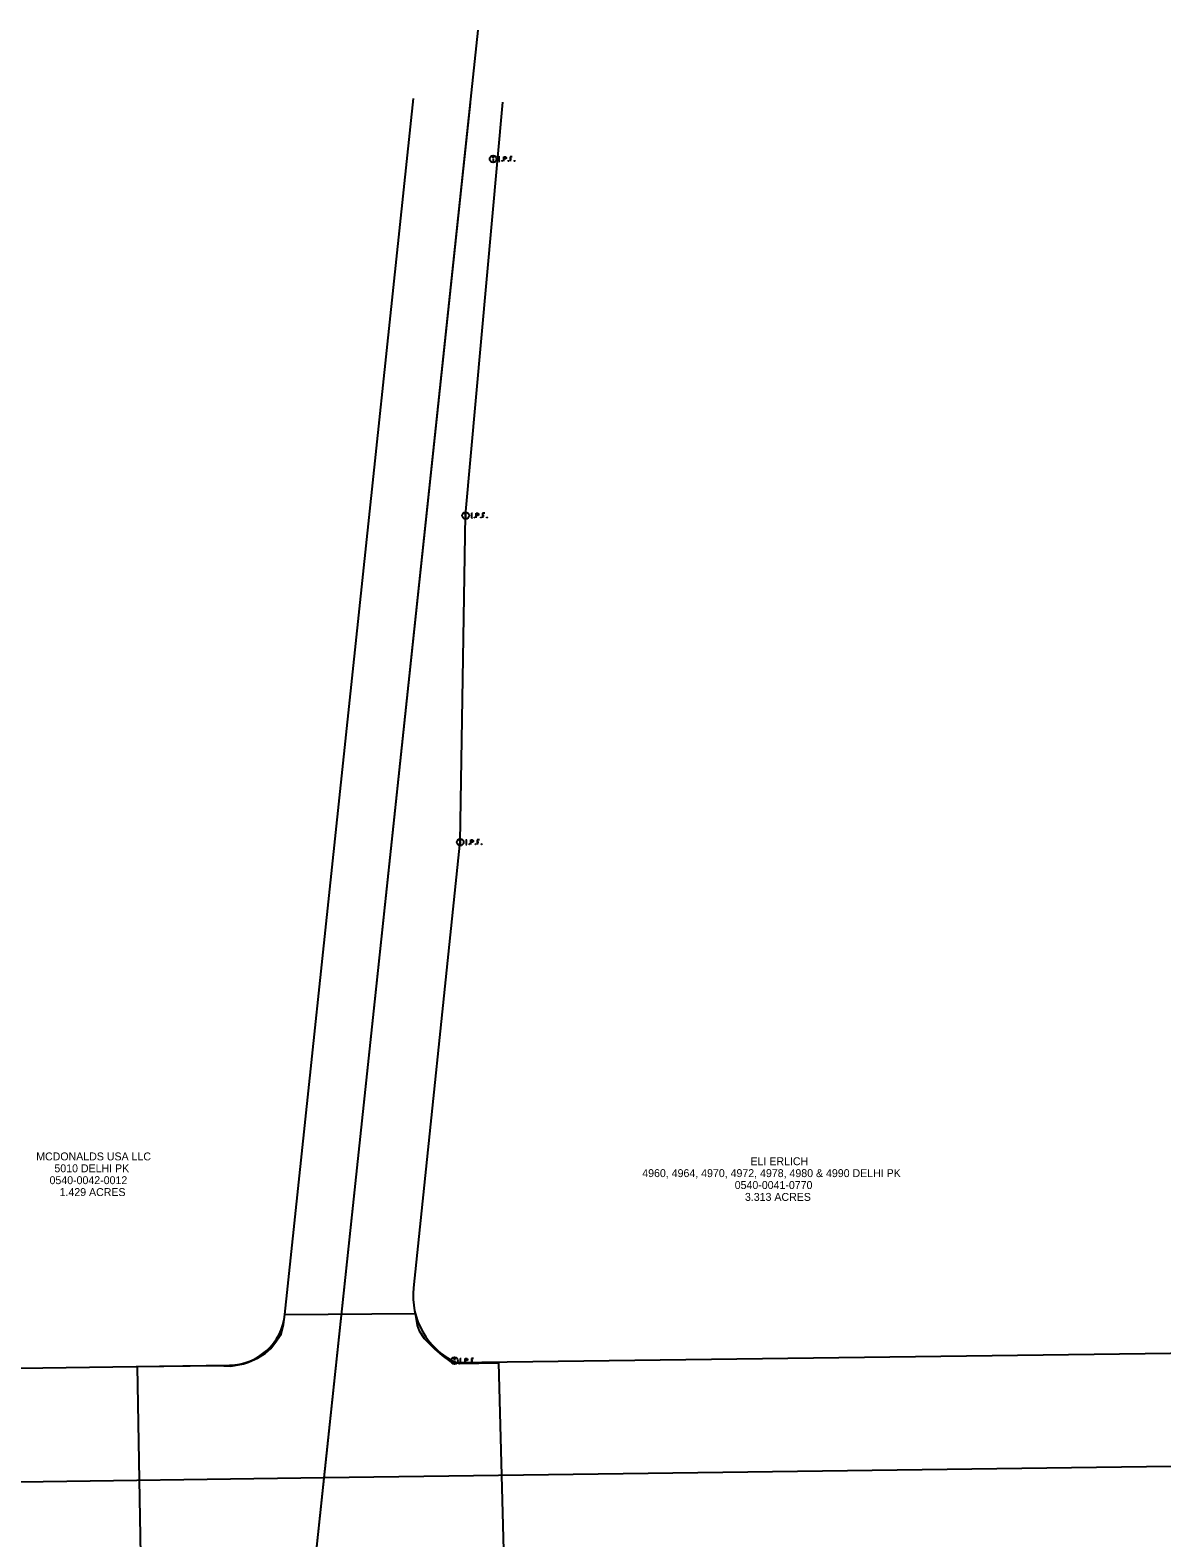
# Model space of a CAD drawing. Extents: x 1369159 to 1370720, y 404461 to 406422.
# Drawn here: x 1369920 to 1370320, y 405889 to 406422 of the extents above; entities that cross this region are included whole.
import ezdxf

# ---------------------------------------------------------------- set-up
doc = ezdxf.new("R2010")
doc.units = 0
for name, color, linetype in [('DR_P_Cells', 7, 'Continuous'), ('DR_X_Cells', 7, 'Continuous'), ('GK_Drainage_Nodes', 7, 'Continuous'), ('SC_Scratch1', 7, 'Continuous'), ('XS_X_Pavt', 7, 'Continuous'), ('XS_X_Subgrade', 7, 'Continuous')]:
    doc.layers.add(name, color=color, linetype=linetype)

msp = doc.modelspace()

# ---------------------------------------------------------------- linework, layer by layer
at = {"layer": 'DR_P_Cells'}
msp.add_line((1370077.92, 406421.94), (1369968.9, 405398.85), dxfattribs=at)
at = {"layer": 'DR_X_Cells'}
msp.add_lwpolyline([(1369959, 405869.67), (1369957.54, 405949.66), (1369985.54, 405950.07), (1369990.57, 405949.81), (1369995.08, 405950.56), (1369996.84, 405951.24), (1369999.97, 405952.63), (1370002.78, 405954.43), (1370004.68, 405955.98), (1370006.08, 405957.97), (1370008.33, 405961.08), (1370009.2, 405964.47), (1370009.68, 405968.04), (1370055.77, 405968.35), (1370056.38, 405964.22), (1370057.1, 405962.29), (1370058.87, 405959.59), (1370062.52, 405955.91), (1370065.31, 405953.6), (1370067.96, 405951.53), (1370070.19, 405951.11), (1370071.35, 405950.7), (1370085.17, 405950.93), (1370087.31, 405871.45)], dxfattribs=at)
at = {"layer": 'SC_Scratch1'}
for p, q in [((1370083.26, 406376.52), (1370083.26, 406375.64)), ((1370085.3, 406377.2), (1370085.65, 406377.2)), ((1370085.3, 406375.6), (1370085.65, 406375.6)), ((1370085.47, 406375.6), (1370085.47, 406377.2)), ((1370086.36, 406375.74), (1370086.4, 406375.79)), ((1370086.36, 406375.68), (1370086.36, 406375.74)), ((1370086.4, 406375.63), (1370086.36, 406375.68)), ((1370086.4, 406375.79), (1370086.43, 406375.82)), ((1370086.43, 406375.6), (1370086.4, 406375.63)), ((1370086.43, 406375.82), (1370086.49, 406375.82)), ((1370086.49, 406375.6), (1370086.43, 406375.6)), ((1370086.49, 406375.82), (1370086.52, 406375.79)), ((1370086.52, 406375.63), (1370086.49, 406375.6)), ((1370086.52, 406375.79), (1370086.55, 406375.74)), ((1370086.55, 406375.68), (1370086.52, 406375.63)), ((1370086.55, 406375.74), (1370086.55, 406375.68)), ((1370087.04, 406375.6), (1370087.04, 406377.2)), ((1370087.04, 406377.2), (1370087.57, 406377.2)), ((1370087.57, 406376.42), (1370087.04, 406376.42)), ((1370087.57, 406377.2), (1370087.62, 406377.19)), ((1370087.65, 406376.43), (1370087.57, 406376.42)), ((1370087.62, 406377.19), (1370087.7, 406377.16)), ((1370087.71, 406376.46), (1370087.65, 406376.43)), ((1370087.7, 406377.16), (1370087.73, 406377.14)), ((1370087.74, 406376.48), (1370087.71, 406376.46)), ((1370087.73, 406377.14), (1370087.76, 406377.11)), ((1370087.79, 406376.52), (1370087.74, 406376.48)), ((1370087.76, 406377.11), (1370087.81, 406377.05)), ((1370087.83, 406376.61), (1370087.79, 406376.52)), ((1370087.81, 406377.05), (1370087.84, 406376.99)), ((1370087.85, 406376.69), (1370087.83, 406376.61)), ((1370087.84, 406376.99), (1370087.86, 406376.89)), ((1370087.86, 406376.74), (1370087.85, 406376.69)), ((1370087.86, 406376.89), (1370087.86, 406376.74)), ((1370088.61, 406375.74), (1370088.65, 406375.79)), ((1370088.61, 406375.68), (1370088.61, 406375.74)), ((1370088.65, 406375.63), (1370088.61, 406375.68)), ((1370088.65, 406375.79), (1370088.68, 406375.82)), ((1370088.68, 406375.6), (1370088.65, 406375.63)), ((1370088.68, 406375.82), (1370088.73, 406375.82)), ((1370088.73, 406375.6), (1370088.68, 406375.6)), ((1370088.73, 406375.82), (1370088.77, 406375.79)), ((1370088.77, 406375.63), (1370088.73, 406375.6)), ((1370088.77, 406375.79), (1370088.8, 406375.74)), ((1370088.8, 406375.68), (1370088.77, 406375.63)), ((1370088.8, 406375.74), (1370088.8, 406375.68)), ((1370090.05, 406377.2), (1370089.29, 406377.2)), ((1370089.29, 406377.2), (1370089.29, 406375.6)), ((1370089.29, 406376.42), (1370089.83, 406376.42)), ((1370090.76, 406375.74), (1370090.8, 406375.79)), ((1370090.76, 406375.68), (1370090.76, 406375.74)), ((1370090.8, 406375.63), (1370090.76, 406375.68)), ((1370090.8, 406375.79), (1370090.83, 406375.82)), ((1370090.83, 406375.6), (1370090.8, 406375.63)), ((1370090.83, 406375.82), (1370090.88, 406375.82)), ((1370090.88, 406375.6), (1370090.83, 406375.6)), ((1370090.88, 406375.82), (1370090.92, 406375.79)), ((1370090.92, 406375.63), (1370090.88, 406375.6)), ((1370090.92, 406375.79), (1370090.95, 406375.74)), ((1370090.95, 406375.68), (1370090.92, 406375.63)), ((1370090.95, 406375.74), (1370090.95, 406375.68)), ((1370073.55, 406250.51), (1370073.55, 406249.63)), ((1370075.58, 406251.2), (1370075.94, 406251.2)), ((1370075.58, 406249.6), (1370075.94, 406249.6)), ((1370075.76, 406249.6), (1370075.76, 406251.2)), ((1370076.65, 406249.73), (1370076.69, 406249.79)), ((1370076.65, 406249.67), (1370076.65, 406249.73)), ((1370076.69, 406249.62), (1370076.65, 406249.67)), ((1370076.69, 406249.79), (1370076.72, 406249.81)), ((1370076.72, 406249.6), (1370076.69, 406249.62)), ((1370076.72, 406249.81), (1370076.77, 406249.81)), ((1370076.77, 406249.6), (1370076.72, 406249.6)), ((1370076.77, 406249.81), (1370076.81, 406249.79)), ((1370076.81, 406249.62), (1370076.77, 406249.6)), ((1370076.81, 406249.79), (1370076.84, 406249.73)), ((1370076.84, 406249.67), (1370076.81, 406249.62)), ((1370076.84, 406249.73), (1370076.84, 406249.67)), ((1370077.33, 406249.6), (1370077.33, 406251.2)), ((1370077.33, 406251.2), (1370077.86, 406251.2)), ((1370077.86, 406250.41), (1370077.33, 406250.41)), ((1370077.86, 406251.2), (1370077.91, 406251.18)), ((1370077.94, 406250.43), (1370077.86, 406250.41)), ((1370077.91, 406251.18), (1370077.99, 406251.16)), ((1370078, 406250.45), (1370077.94, 406250.43)), ((1370077.99, 406251.16), (1370078.02, 406251.13)), ((1370078.03, 406250.48), (1370078, 406250.45)), ((1370078.02, 406251.13), (1370078.05, 406251.11)), ((1370078.08, 406250.52), (1370078.03, 406250.48)), ((1370078.05, 406251.11), (1370078.1, 406251.04)), ((1370078.12, 406250.6), (1370078.08, 406250.52)), ((1370078.1, 406251.04), (1370078.13, 406250.98)), ((1370078.14, 406250.68), (1370078.12, 406250.6)), ((1370078.13, 406250.98), (1370078.15, 406250.88)), ((1370078.15, 406250.73), (1370078.14, 406250.68)), ((1370078.15, 406250.88), (1370078.15, 406250.73)), ((1370078.9, 406249.73), (1370078.94, 406249.79)), ((1370078.9, 406249.67), (1370078.9, 406249.73)), ((1370078.94, 406249.62), (1370078.9, 406249.67)), ((1370078.94, 406249.79), (1370078.97, 406249.81)), ((1370078.97, 406249.6), (1370078.94, 406249.62)), ((1370078.97, 406249.81), (1370079.02, 406249.81)), ((1370079.02, 406249.6), (1370078.97, 406249.6)), ((1370079.02, 406249.81), (1370079.06, 406249.79)), ((1370079.06, 406249.62), (1370079.02, 406249.6)), ((1370079.06, 406249.79), (1370079.09, 406249.73)), ((1370079.09, 406249.67), (1370079.06, 406249.62)), ((1370079.09, 406249.73), (1370079.09, 406249.67)), ((1370080.34, 406251.2), (1370079.57, 406251.2)), ((1370079.57, 406251.2), (1370079.57, 406249.6)), ((1370079.57, 406250.41), (1370080.11, 406250.41)), ((1370081.05, 406249.73), (1370081.08, 406249.79)), ((1370081.05, 406249.67), (1370081.05, 406249.73)), ((1370081.08, 406249.62), (1370081.05, 406249.67)), ((1370081.08, 406249.79), (1370081.12, 406249.81)), ((1370081.12, 406249.6), (1370081.08, 406249.62)), ((1370081.12, 406249.81), (1370081.17, 406249.81)), ((1370081.17, 406249.6), (1370081.12, 406249.6)), ((1370081.17, 406249.81), (1370081.21, 406249.79)), ((1370081.21, 406249.62), (1370081.17, 406249.6)), ((1370081.21, 406249.79), (1370081.24, 406249.73)), ((1370081.24, 406249.67), (1370081.21, 406249.62)), ((1370081.24, 406249.73), (1370081.24, 406249.67)), ((1370071.65, 406135.06), (1370071.65, 406134.17)), ((1370073.68, 406135.74), (1370074.03, 406135.74)), ((1370073.68, 406134.14), (1370074.03, 406134.14)), ((1370073.85, 406134.14), (1370073.85, 406135.74)), ((1370074.75, 406134.28), (1370074.78, 406134.33)), ((1370074.75, 406134.21), (1370074.75, 406134.28)), ((1370074.78, 406134.16), (1370074.75, 406134.21)), ((1370074.78, 406134.33), (1370074.81, 406134.35)), ((1370074.81, 406134.14), (1370074.78, 406134.16)), ((1370074.81, 406134.35), (1370074.87, 406134.35)), ((1370074.87, 406134.14), (1370074.81, 406134.14)), ((1370074.87, 406134.35), (1370074.9, 406134.33)), ((1370074.9, 406134.16), (1370074.87, 406134.14)), ((1370074.9, 406134.33), (1370074.93, 406134.28)), ((1370074.93, 406134.21), (1370074.9, 406134.16)), ((1370074.93, 406134.28), (1370074.93, 406134.21)), ((1370075.42, 406134.14), (1370075.42, 406135.74)), ((1370075.42, 406135.74), (1370075.95, 406135.74)), ((1370075.95, 406134.96), (1370075.42, 406134.96)), ((1370075.95, 406135.74), (1370076, 406135.73)), ((1370076.04, 406134.97), (1370075.95, 406134.96)), ((1370076, 406135.73), (1370076.08, 406135.7)), ((1370076.09, 406135), (1370076.04, 406134.97)), ((1370076.08, 406135.7), (1370076.11, 406135.68)), ((1370076.12, 406135.02), (1370076.09, 406135)), ((1370076.11, 406135.68), (1370076.15, 406135.65)), ((1370076.17, 406135.06), (1370076.12, 406135.02)), ((1370076.15, 406135.65), (1370076.19, 406135.59)), ((1370076.21, 406135.15), (1370076.17, 406135.06)), ((1370076.19, 406135.59), (1370076.22, 406135.52)), ((1370076.23, 406135.22), (1370076.21, 406135.15)), ((1370076.22, 406135.52), (1370076.25, 406135.42)), ((1370076.25, 406135.27), (1370076.23, 406135.22)), ((1370076.25, 406135.42), (1370076.25, 406135.27)), ((1370077, 406134.28), (1370077.03, 406134.33)), ((1370077, 406134.21), (1370077, 406134.28)), ((1370077.03, 406134.16), (1370077, 406134.21)), ((1370077.03, 406134.33), (1370077.06, 406134.35)), ((1370077.06, 406134.14), (1370077.03, 406134.16)), ((1370077.06, 406134.35), (1370077.12, 406134.35)), ((1370077.12, 406134.14), (1370077.06, 406134.14)), ((1370077.12, 406134.35), (1370077.15, 406134.33)), ((1370077.15, 406134.16), (1370077.12, 406134.14)), ((1370077.15, 406134.33), (1370077.18, 406134.28)), ((1370077.18, 406134.21), (1370077.15, 406134.16)), ((1370077.18, 406134.28), (1370077.18, 406134.21)), ((1370078.43, 406135.74), (1370077.67, 406135.74)), ((1370077.67, 406135.74), (1370077.67, 406134.14)), ((1370077.67, 406134.96), (1370078.21, 406134.96)), ((1370079.14, 406134.28), (1370079.18, 406134.33)), ((1370079.14, 406134.21), (1370079.14, 406134.28)), ((1370079.18, 406134.16), (1370079.14, 406134.21)), ((1370079.18, 406134.33), (1370079.21, 406134.35)), ((1370079.21, 406134.14), (1370079.18, 406134.16)), ((1370079.21, 406134.35), (1370079.27, 406134.35)), ((1370079.27, 406134.14), (1370079.21, 406134.14)), ((1370079.27, 406134.35), (1370079.3, 406134.33)), ((1370079.3, 406134.16), (1370079.27, 406134.14)), ((1370079.3, 406134.33), (1370079.33, 406134.28)), ((1370079.33, 406134.21), (1370079.3, 406134.16)), ((1370079.33, 406134.28), (1370079.33, 406134.21)), ((1370069.59, 405951.84), (1370069.59, 405950.96)), ((1370071.62, 405952.52), (1370071.97, 405952.52)), ((1370071.8, 405950.92), (1370071.8, 405952.52)), ((1370072.72, 405951.11), (1370072.76, 405951.14)), ((1370072.76, 405951.14), (1370072.81, 405951.14)), ((1370072.81, 405951.14), (1370072.84, 405951.11)), ((1370073.36, 405950.92), (1370073.36, 405952.52)), ((1370073.36, 405952.52), (1370073.89, 405952.52)), ((1370073.89, 405951.74), (1370073.36, 405951.74)), ((1370073.89, 405952.52), (1370073.95, 405952.51)), ((1370073.98, 405951.76), (1370073.89, 405951.74)), ((1370073.95, 405952.51), (1370074.02, 405952.49)), ((1370074.03, 405951.78), (1370073.98, 405951.76)), ((1370074.02, 405952.49), (1370074.06, 405952.46)), ((1370074.07, 405951.81), (1370074.03, 405951.78)), ((1370074.06, 405952.46), (1370074.09, 405952.44)), ((1370074.11, 405951.84), (1370074.07, 405951.81)), ((1370074.09, 405952.44), (1370074.13, 405952.37)), ((1370074.16, 405951.93), (1370074.11, 405951.84)), ((1370074.13, 405952.37), (1370074.17, 405952.31)), ((1370074.18, 405952.01), (1370074.16, 405951.93)), ((1370074.17, 405952.31), (1370074.19, 405952.21)), ((1370074.19, 405952.06), (1370074.18, 405952.01)), ((1370074.19, 405952.21), (1370074.19, 405952.06)), ((1370074.97, 405951.11), (1370075, 405951.14)), ((1370075, 405951.14), (1370075.06, 405951.14)), ((1370075.06, 405951.14), (1370075.09, 405951.11)), ((1370076.37, 405952.52), (1370075.61, 405952.52)), ((1370075.61, 405952.52), (1370075.61, 405950.92)), ((1370075.61, 405951.74), (1370076.15, 405951.74)), ((1370077.12, 405951.11), (1370077.15, 405951.14)), ((1370077.15, 405951.14), (1370077.21, 405951.14)), ((1370077.21, 405951.14), (1370077.24, 405951.11)), ((1370071.62, 405950.92), (1370071.97, 405950.92)), ((1370072.69, 405951.06), (1370072.72, 405951.11)), ((1370072.69, 405951), (1370072.69, 405951.06)), ((1370072.72, 405950.95), (1370072.69, 405951)), ((1370072.76, 405950.92), (1370072.72, 405950.95)), ((1370072.81, 405950.92), (1370072.76, 405950.92)), ((1370072.84, 405950.95), (1370072.81, 405950.92)), ((1370072.84, 405951.11), (1370072.88, 405951.06)), ((1370072.88, 405951), (1370072.84, 405950.95)), ((1370072.88, 405951.06), (1370072.88, 405951)), ((1370074.94, 405951.06), (1370074.97, 405951.11)), ((1370074.94, 405951), (1370074.94, 405951.06)), ((1370074.97, 405950.95), (1370074.94, 405951)), ((1370075, 405950.92), (1370074.97, 405950.95)), ((1370075.06, 405950.92), (1370075, 405950.92)), ((1370075.09, 405950.95), (1370075.06, 405950.92)), ((1370075.09, 405951.11), (1370075.13, 405951.06)), ((1370075.13, 405951), (1370075.09, 405950.95)), ((1370075.13, 405951.06), (1370075.13, 405951)), ((1370077.09, 405951.06), (1370077.12, 405951.11)), ((1370077.09, 405951), (1370077.09, 405951.06)), ((1370077.12, 405950.95), (1370077.09, 405951)), ((1370077.15, 405950.92), (1370077.12, 405950.95)), ((1370077.21, 405950.92), (1370077.15, 405950.92)), ((1370077.24, 405950.95), (1370077.21, 405950.92)), ((1370077.24, 405951.11), (1370077.28, 405951.06)), ((1370077.28, 405951), (1370077.24, 405950.95)), ((1370077.28, 405951.06), (1370077.28, 405951))]:
    msp.add_line(p, q, dxfattribs=at)
for centre, radius in [((1370083.26, 406376.4), 1.2), ((1370083.26, 406377.05), 0.16), ((1370073.55, 406250.4), 1.2), ((1370073.55, 406251.05), 0.16), ((1370071.65, 406134.94), 1.2), ((1370071.65, 406135.59), 0.16), ((1370069.59, 405951.72), 1.2), ((1370069.59, 405952.38), 0.16)]:
    msp.add_circle(centre, radius, dxfattribs=at)
at = {"layer": 'XS_X_Pavt'}
for p, q in [((1370075.13, 406396.09), (1370023.41, 405910.39)), ((1370023.59, 405910.4), (1370508.58, 405916.92)), ((1369788.56, 405907.22), (1370023.59, 405910.4)), ((1370023.41, 405910.39), (1369966.45, 405374.29))]:
    msp.add_line(p, q, dxfattribs=at)
at = {"layer": 'XS_X_Subgrade'}
for p, q in [((1370009.68, 405968.02), (1370055.1, 406397.78)), ((1370086.63, 406396.48), (1370073.4, 406250.59)), ((1370073.4, 406250.59), (1370071.54, 406135.11)), ((1370071.54, 406135.11), (1370055.11, 405977.52)), ((1370070.19, 405951.11), (1370596.72, 405957.84)), ((1369787.95, 405947.22), (1369990.08, 405950.13))]:
    msp.add_line(p, q, dxfattribs=at)
for centre, radius, start, end in [((1370080.96, 405974.76), 25.99, 173.9136, 245.5139), ((1369989.79, 405970.13), 20, 270.826, 353.9432)]:
    msp.add_arc(centre, radius, start, end, dxfattribs=at)

# ---------------------------------------------------------------- texts
at = {"layer": 'GK_Drainage_Nodes'}
for s, p in [('MCDONALDS USA LLC', (1369921.76, 406022.52)), ('5010 DELHI PK', (1369928.19, 406018.32)), ('ELI ERLICH', (1370174.26, 406020.81)), ('0540-0042-0012', (1369926.46, 406014.12)), ('4960, 4964, 4970, 4972, 4978, 4980 & 4990 DELHI PK', (1370136, 406016.61)), ('0540-0041-0770', (1370168.68, 406012.41)), ('1.429 ACRES', (1369930.02, 406009.92)), ('3.313 ACRES', (1370172.3, 406008.21))]:
    msp.add_text(s, height=2.8, dxfattribs=at).set_placement(p)

doc.saveas('drawing.dxf')
